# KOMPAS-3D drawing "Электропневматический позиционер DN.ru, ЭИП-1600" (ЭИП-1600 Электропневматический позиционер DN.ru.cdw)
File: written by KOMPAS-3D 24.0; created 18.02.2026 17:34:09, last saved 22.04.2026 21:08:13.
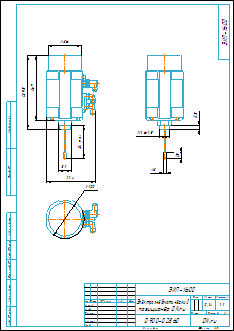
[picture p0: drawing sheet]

Document properties: Автор: R2D2; Форматы листов документа: A3; Полное имя файла: ЭИП-1600 Электропневматический позиционер DN.ru.m3d; Масса: 0.14; Наименование: Электропневматический позиционер DN.ru; Количество листов документа: 1; Примечание: D900-02860

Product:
- Part/product: Электропневматический позиционер DN.ru  | designation ЭИП-1600
    Масса: 0.14
    Раздел спецификации: Прочие изделия
    Примечание: D900-02860

Views: Проекционный вид 2
Referenced files in E:\Работа\Зайцев\Аксессуары для пневмоприводов\Электропневматические позиционеры DN.ru\ЭИП Электропневматический позиционер DN.ru\ЭИП-1600 Электропневматический позиционер DN.ru\5-25\: ЭИП-1600 Электропневматический позиционер DN.ru.m3d
Referenced files in E:\Работа\Зайцев\Для компаса\: чертеж DN.ru А3.cdt
Referenced files in E:\Работа\Зайцев\Аксессуары для пневмоприводов\Электропневматические позиционеры DN.ru\ЭИП Электропневматический позиционер DN.ru\ЭИП-1600 Электропневматический позиционер DN.ru\25-50\: ЭИП-1600 Электропневматический позиционер DN.ru.m3d
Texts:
  ЭИП-1600
  чертеж DN.ru А3.cdt
  Электропневматический
  позиционер DN.ru
  Электропневматический позиционер DN.ru
  ЭИП-1600 Электропневматический позиционер DN.ru
Dimensions and other numbers on the sheet: 0; 3; 4; 11,5; 15; 8; 26; 1:2; 1; 2; 0,14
